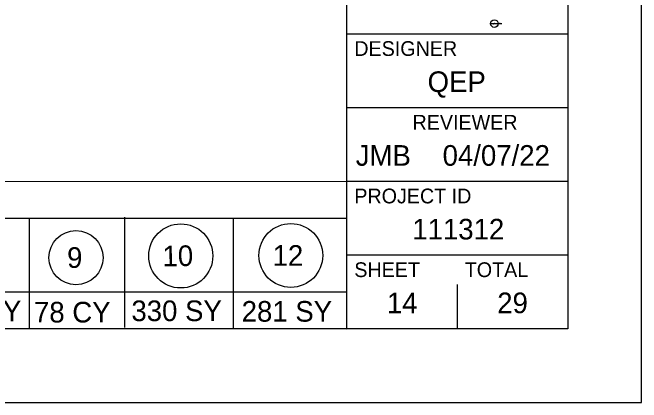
# Model space of a CAD drawing. Extents: x 0 to 34, y 0 to 22.
# Drawn here: x 29.729 to 34, y 0 to 2.644 of the extents above; entities that cross this region are included whole.
import ezdxf

# ---------------------------------------------------------------- set-up
doc = ezdxf.new("R2010")
doc.units = 0
for name, color, linetype in [('CS-ALGN-TEXT', 7, 'Continuous'), ('CS-ANNO', 7, 'Continuous'), ('CS-ANNO-MATC', 7, 'Continuous'), ('CS-ANNO-MATC-TEXT', 7, 'Continuous'), ('CS-ANNO-TABL', 7, 'Continuous')]:
    doc.layers.add(name, color=color, linetype=linetype)

msp = doc.modelspace()

# ---------------------------------------------------------------- linework, layer by layer
at = {"layer": 'CS-ALGN-TEXT'}
for p, q in [((24.8745, 1.4961), (32, 1.5)), ((24.8745, 1.25), (32, 1.25)), ((29.8426, 0.5006), (29.8426, 1.2506)), ((30.4912, 0.5074), (30.4912, 1.2574)), ((31.2286, 0.5), (31.2286, 1.25)), ((32.75, 0.5), (32.75, 0.8)), ((24.8745, 0.75), (32, 0.75)), ((32.375, 0.675), (32.375, 0.675)), ((27.2496, 0.5004), (32, 0.5))]:
    msp.add_line(p, q, dxfattribs=at)
at = {"layer": 'CS-ANNO'}
msp.add_lwpolyline([(0, 0), (34, 0), (34, 22), (0, 22)], close=True, dxfattribs=at)
at = {"layer": 'CS-ANNO-MATC'}
for p, q in [((32, 0.5), (32, 21.5)), ((32, 2.5), (33.5, 2.5)), ((32, 2), (33.5, 2)), ((32, 1.5), (33.5, 1.5)), ((32, 1), (33.5, 1))]:
    msp.add_line(p, q, dxfattribs=at)
msp.add_lwpolyline([(1.5, 21.5), (33.5, 21.5), (33.5, 0.5), (1.5, 0.5)], close=True, dxfattribs=at)
at = {"layer": 'CS-ANNO-MATC-TEXT'}
for centre, radius in [((30.8712, 0.9935), 0.2175), ((31.6186, 0.9968), 0.2165), ((30.1595, 0.9816), 0.1837)]:
    msp.add_circle(centre, radius, dxfattribs=at)
at = {"layer": 'CS-ANNO-TABL'}
for p, q in [((32.9756, 2.5695), (33.0277, 2.5695)), ((33.0018, 2.5695), (33.0513, 2.5695))]:
    msp.add_line(p, q, dxfattribs=at)
msp.add_circle((33.0016, 2.5695), 0.026, dxfattribs=at)

# ---------------------------------------------------------------- texts
at = {"layer": 'CS-ALGN-TEXT'}
for s, height, p in [('DESIGNER', 0.1, (32.05, 2.35)), ('QEP', 0.14, (32.5477, 2.105)), ('REVIEWER', 0.1, (32.4454, 1.85)), ('04/07/22', 0.14, (32.6497, 1.605)), ('JMB', 0.14, (32.0596, 1.605)), ('PROJECT ID', 0.1, (32.05, 1.35)), ('111312', 0.14, (32.4435, 1.105)), ('SHEET', 0.1, (32.05, 0.85)), ('TOTAL', 0.1, (32.8, 0.85)), ('14', 0.14, (32.271, 0.605)), ('29', 0.14, (33.0206, 0.605))]:
    msp.add_text(s, height=height, dxfattribs=at).set_placement(p)
at = {"layer": 'CS-ANNO-MATC-TEXT'}
for s, p in [('12', (31.4948, 0.9266)), ('9', (30.099, 0.9125)), ('58 CY', (29.2671, 0.5492)), ('78 CY', (29.8742, 0.542)), ('330 SY', (30.5359, 0.5513)), ('281 SY', (31.2848, 0.5475))]:
    msp.add_text(s, height=0.14, dxfattribs=at).set_placement(p)
msp.add_text('10', height=0.14, rotation=1, dxfattribs=at).set_placement((30.7484, 0.9222))
at = {"layer": 'CS-ANNO-TABL'}
for s, p in [('4+00.00', (32.9936, 2.5596)), ('1', (33.0008, 2.576)), ('1:2', (33.0344, 2.5596)), ('Drawing', (33.0344, 2.576))]:
    msp.add_text(s, height=0.00328, dxfattribs=at).set_placement(p)

doc.saveas('drawing.dxf')
